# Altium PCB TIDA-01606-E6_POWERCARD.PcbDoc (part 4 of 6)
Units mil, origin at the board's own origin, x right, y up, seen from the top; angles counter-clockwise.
Board outline 13779.53 x 7874.02 mil, 4 copper layers (Top Layer, Gnd Layer, Pwr Layer, Bottom Layer), stack 94.4 mil thick; 550 components, 292 nets, 1594 pads, 572 vias.
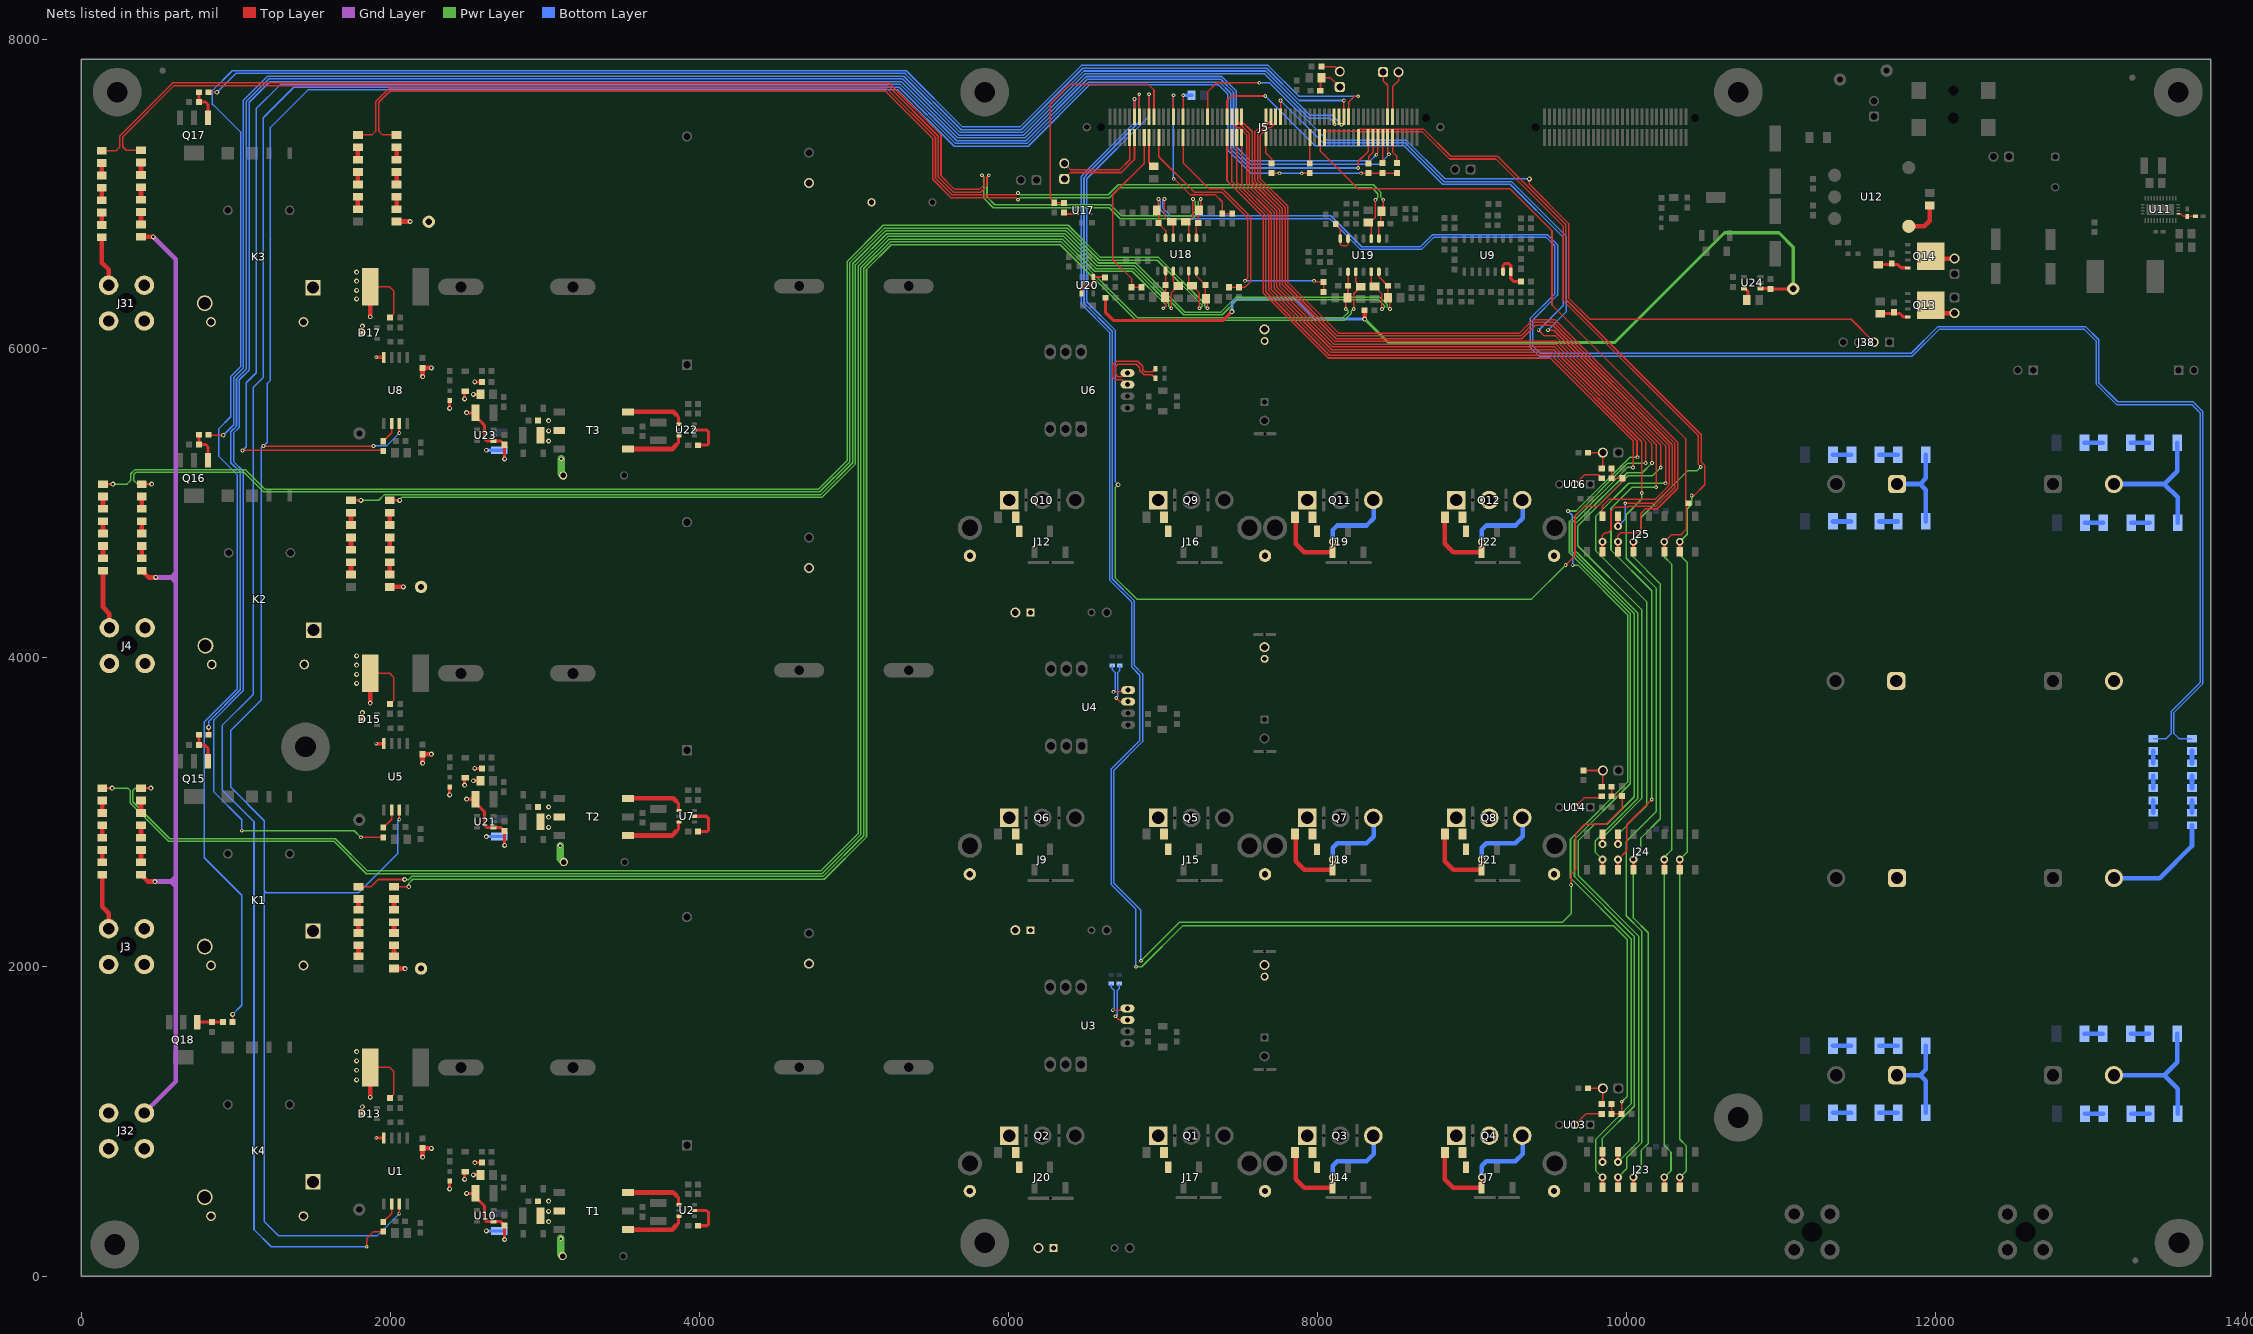
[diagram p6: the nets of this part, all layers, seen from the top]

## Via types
v1: diameter 32, hole 16, Top Layer to Bottom Layer, 336 vias
v2: diameter 24, hole 12, Top Layer to Bottom Layer, 140 vias
v3: diameter 50, hole 28, Top Layer to Bottom Layer, tented both sides, 65 vias
v4: diameter 52, hole 28, Top Layer to Bottom Layer, 14 vias
v5: diameter 19.68, hole 7.87, Top Layer to Bottom Layer, 10 vias
v6: diameter 50, hole 28, Top Layer to Bottom Layer, 7 vias

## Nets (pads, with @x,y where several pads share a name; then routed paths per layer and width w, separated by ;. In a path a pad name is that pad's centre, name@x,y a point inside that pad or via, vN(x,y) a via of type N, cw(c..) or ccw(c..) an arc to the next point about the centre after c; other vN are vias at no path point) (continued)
NetJ5_9: J5.9 J6.2 | length 609.7
  Top Layer w10: J6.2@6361,7199 6401,7159 6720.72,7159 6783.97,7222.25 J5.9@6783.97,7366.21
NetJ5_11: J5.11 J6.1 | length 647.6
  Top Layer w10: J6.1@6361,7099 6402,7140 6730,7140 6815.47,7225.47 J5.11@6815.47,7366.21
NetJ5_17: J5.17 R195.1 | length 205
  Top Layer w12: J5.17@6909.96,7366.21 6909.96,7203.06 R195.1@6939.55,7173.46
NetJ5_32: J5.32 R196.1 | length 200
  Top Layer w10: J5.32@7130.43,7500.07 v2@7130.43,7639.57
  Bottom Layer w20: v2@7130,7640 R196.1@7190.53,7640
  other v2: 7129.99,7640.01
NetJ5_57: J5.57 R34.2 | length 179.7
  Top Layer w10: J5.57@7665.86,7366.21 7665.86,7264.61 7702,7228.47 R34.2@7702,7201.46
NetJ5_75: J5.75 R36.2 | length 165
  Top Layer w10: R36.2@7948.7,7201.46 7949.33,7202.09 J5.75@7949.33,7366.21
NetJ5_101: J5.101 R163.2 | length 183.7
  Top Layer w10: R163.2@8325,7201.46 R163.2@8330,7206.46 ; R163.2@8330,7201.46 R163.2@8330,7206.46 ; J5.101@8358.78,7366.21 8358.77,7270.37 8330,7241.59 R163.2@8330,7206.46
NetJ5_105: J5.105 R164.2 | length 164.5
  Top Layer w10: R164.2@8420,7202.46 8421.77,7204.23 J5.105@8421.77,7366.21
NetJ5_108: J5.108 J11.1 | length 301.2
  Top Layer w10: J11.1@8423.7,7789 8423.7,7733.3 8453.26,7703.74 J5.108@8453.26,7500.07
NetJ5_109: J5.109 R165.2 | length 175.4
  Top Layer w10: J5.109@8484.76,7366.21 8484.76,7273.24 8513,7245 R165.2@8513,7202.46
NetJ5_110: J5.110 J11.2 | length 305.1
  Top Layer w10: J5.110@8484.76,7500.07 8484.76,7694.36 8523.7,7733.3 J11.2@8523.7,7789
NetJ10_1: J10.1 R35.1 R37.1 | length 235.5
  Top Layer w10: R37.1@8017.13,7669 8019.09,7669 8018.79,7669.3 8018.79,7753 8083.33,7753 J10.1@8143.33,7693
NetJ10_2: J10.2 R38.2 | length 132.8
  Top Layer w10: R38.2@8023.83,7825 8111.33,7825 J10.2@8143.33,7793
NetJ26_2: J26.2 Q13.5 Q13.6 Q13.7 Q13.8 Q13.9@11966.81,6281 | length 181
  Top Layer w30: Q13.9@11940,6230 J26.2@12121,6230
NetJ27_2: J27.2 R55.1 R58.1 | length 190
  Top Layer w10: R55.1@9750,1215.2 J27.2@9845,1215.2 R58.1@9845,1120.24
NetJ28_2: J28.2 Q14.5 Q14.6 Q14.7 Q14.8 Q14.9@11967.57,6597.75 | length 173.2
  Top Layer w30: Q14.9@11948.8,6583 J28.2@12121.99,6583
NetJ29_2: J29.2 R64.1 R65.1 | length 223.3
  Top Layer w10: R64.1@9720.23,3271.27 J29.2@9845,3271.27 R65.1@9845,3172.76
NetJ30_2: J30.2 R91.1 R92.1 | length 202.7
  Top Layer w10: R91.1@9750,5327.33 J30.2@9845,5327.33 9845,5240.87 R92.1@9830,5225.87
NetQ13_4: Q13.4 R59.2 R60.2 | length 185.7
  Top Layer w20: R59.2@11640.79,6226 11642.04,6227.25 11767.25,6227.25 11788.5,6206 Q13.4@11817.2,6206
NetQ14_4: Q14.4 R66.2 R76.2 | length 185.7
  Top Layer w20: R66.2@11626.54,6543.76 11627.79,6545 11753,6545 11774.25,6523.76 Q14.4@11802.96,6523.76
NetQ15_1: Q15.1 R197.2 R201.2 | length 217.3
  Top Layer w20: R197.2@762.5,3501.99 R201.2@762.5,3436 800,3436 821.55,3414.45 Q15.1@821.55,3331.17
NetQ16_1: Q16.1 R198.2 R204.2 | length 216.8
  Top Layer w20: R198.2@762.5,5443.99 R204.2@762.5,5380 806,5380 821.55,5364.45 Q16.1@821.55,5277.17
NetQ17_1: Q17.1 R199.2 R202.2 | length 214.2
  Top Layer w20: R199.2@762.5,7658.99 R202.2@762.5,7596 805,7596 821.55,7579.45 Q17.1@821.55,7494.17
NetQ18_1: Q18.1 R200.2 R203.2 | length 166.3
  Top Layer w20: Q18.1@751.55,1643.17 847.68,1643.17 R203.2@848,1643.5 917,1643.5 R200.2@917.5,1644
NetR1_1: R1.1 R3.2 | length 118.9
  Bottom Layer w30: R1.1@12961.25,5392.45 R3.2@13080.15,5392.45
NetR2_1: R2.1 R4.2 | length 118.9
  Bottom Layer w30: R2.1@12964.25,4874.55 R4.2@13083.15,4874.55
NetR3_1: R3.1 R6.2 | length 118.9
  Bottom Layer w30: R3.1@13261.25,5392.45 R6.2@13380.15,5392.45
NetR4_1: R4.1 R7.2 | length 118.9
  Bottom Layer w30: R4.1@13264.25,4874.55 R7.2@13383.15,4874.55
NetR9_1: R9.1 R12.2 | length 118.9
  Bottom Layer w30: R12.2@11634.4,4882.55 R9.1@11753.3,4882.55
NetR10_1: R10.1 R13.2 | length 118.9
  Bottom Layer w30: R13.2@11634.4,5314.45 R10.1@11753.3,5314.45
NetR12_1: R12.1 R14.2 | length 118.9
  Bottom Layer w30: R14.2@11334.4,4882.55 R12.1@11453.3,4882.55
NetR13_1: R13.1 R15.2 | length 118.9
  Bottom Layer w30: R15.2@11334.4,5314.45 R13.1@11453.3,5314.45
NetR19_1: R19.1 U3.11 | length 280
  Top Layer w10: v2(6675.35,1721.06) 6758.26,1721.06 U3.11@6769.7,1732.5
  Bottom Layer w10: R19.1@6665.35,1889.57 6665.35,1866.94 6685.35,1846.94 6685.35,1731.06 v2(6675.35,1721.06)
NetR20_1: R20.1 U3.12 | length 335
  Top Layer w10: v2@6692.61,1683.8 v2(6692.61,1681.06) 6716.17,1657.5 U3.12@6769.7,1657.5
  Bottom Layer w10: v2(6692.61,1681.06) 6703.22,1691.67 6703.22,1846.56 6715.28,1858.62 R20.1@6715.28,1889.57 ; U3.12@6742.5,1657.5 U3.12@6770,1657.5
NetR21_1: R21.1 U4.11 | length 280
  Top Layer w10: v2(6680,3780) 6762.92,3780 U4.11@6774.35,3791.44
  Bottom Layer w10: R21.1@6670,3948.5 6670,3925.87 6690,3905.87 6690,3790 v2(6680,3780)
NetR22_1: R22.1 U4.12 | length 307.5
  Top Layer w10: v2@6697.27,3742.73 v2(6697.27,3740) 6720.83,3716.44 U4.12@6774.35,3716.44
  Bottom Layer w10: v2(6697.27,3740) 6707.87,3750.61 6707.87,3905.5 6719.93,3917.56 R22.1@6719.93,3948.5
NetR23_1: R23.1 U6.11 | length 453.5
  Top Layer w9: U6.11@6770,5842.5 6752.36,5842.5 6729.41,5819.55 6707.71,5819.55 6692.61,5834.65 6692.61,5884.92 6707.69,5900 6828.24,5900 6850,5878.24 6850,5860 6880,5830 6928.5,5830 R23.1@6948.5,5810
NetR24_1: R24.1 U6.12 | length 528
  Top Layer w9: U6.12@6770,5767.5 6763.91,5767.5 6731.41,5800 6690,5800 6675.35,5814.65 6675.35,5895.59 6699.76,5920 6837,5920 6870,5887 6870,5863.86 6882.37,5851.5 6930,5851.5 R24.1@6948.5,5870
NetR42_2: R42.2 R43.1 | length 80
  Top Layer w30: R42.2@137.45,2677 R43.1@137.45,2757
NetR43_2: R43.2 R44.1 | length 80
  Top Layer w30: R43.2@137.45,2837 R44.1@137.45,2917
NetR44_2: R44.2 R45.1 | length 80
  Top Layer w30: R44.2@137.45,2997 R45.1@137.45,3077
NetR48_2: R48.2 R49.1 | length 80
  Top Layer w30: R48.2@388,2677 R49.1@388,2757
NetR49_2: R49.2 R50.1 | length 80
  Top Layer w30: R49.2@388,2837 R50.1@388,2917
NetR50_2: R50.2 R51.1 | length 80
  Top Layer w30: R50.2@388,2997 R51.1@388,3077
NetR52_1: R52.1 U13.2 | length 204.5
  Top Layer w10: U13.2@9663.54,977.94 9734.8,1049.2 R52.1@9838.5,1049.2
NetR54_1: R54.1 R57.2 U11.12 | length 120.1
  Top Layer w10: U11.12@13566.8,6871.62 13586.38,6871.62 13601.62,6856.38 R57.2@13626,6856.38 13679.76,6856.38 R54.1@13680.38,6857
NetR62_1: R62.1 U14.2 | length 204.5
  Top Layer w10: U14.2@9663.54,3034 9723.53,3094 9827.24,3094 R62.1@9838.5,3105.27
NetR67_2: R67.2 R68.1 | length 80
  Top Layer w30: R67.2@142.45,4644 R68.1@142.45,4724
NetR68_2: R68.2 R69.1 | length 80
  Top Layer w30: R68.2@142.45,4804 R69.1@142.45,4884
NetR69_2: R69.2 R70.1 | length 80
  Top Layer w30: R69.2@142.45,4964 R70.1@142.45,5044
NetR72_2: R72.2 U12.4 | length 249.1
  Top Layer w30: U12.4@11824.66,6792.04 11924.04,6792.04 11959.7,6827.7 R72.2@11959.7,6927
NetR73_1: R73.1 R110.2 | length 80
  Top Layer w30: R110.2@393,4644 R73.1@393.01,4724
NetR73_2: R73.2 R74.1 | length 80
  Top Layer w30: R73.2@393.01,4804 R74.1@393,4884
NetR74_2: R74.2 R75.1 | length 80
  Top Layer w30: R74.2@393,4964 R75.1@393,5044
NetR77_1: R77.1 U16.2 | length 212.1
  Top Layer w10: U16.2@9664.61,5122.01 9726.6,5184 9815.83,5184 R77.1@9838.5,5161.33 R77.1@9835.33,5161.33
NetR80_2: R80.2 R81.1 | length 80
  Top Layer w30: R80.2@134.45,6801 R81.1@134.45,6881
NetR81_2: R81.2 R82.1 | length 80
  Top Layer w30: R81.2@134.45,6961 R82.1@134.45,7041
NetR82_2: R82.2 R83.1 | length 80
  Top Layer w30: R82.2@134.45,7121 R83.1@134.45,7201
NetR85_2: R85.2 R86.1 | length 80
  Top Layer w30: R85.2@388,6804 R86.1@388,6884
NetR86_2: R86.2 R87.1 | length 80
  Top Layer w30: R86.2@388,6964 R87.1@388,7044
NetR87_2: R87.2 R88.1 | length 80
  Top Layer w30: R87.2@388,7124 R88.1@388,7204
NetR90_2: R90.2 U2.5 | length 239.7
  Top Layer w20: U2.5@3973.14,425 4045,425 4060,410 4060,336 4050,326 R90.2@3991.5,326
NetR93_1: R93.1 U17.3 | length 81
  Top Layer w15: R93.1@6359,6872 6359.59,6871.41 U17.3@6439.71,6871.41
NetR95_2: R95.2 R96.1 | length 70
  Top Layer w30: R95.2@1795,2070 R96.1@1795,2140
NetR96_2: R96.2 R97.1 | length 70
  Top Layer w30: R96.2@1795,2220 R97.1@1795,2290
NetR97_2: R97.2 R98.1 | length 70
  Top Layer w30: R97.2@1795,2370 R98.1@1795,2440
NetR100_2: R100.2 R101.1 | length 70
  Top Layer w30: R100.2@2025,2070 R101.1@2025,2140
NetR101_2: R101.2 R102.1 | length 70
  Top Layer w30: R101.2@2025,2220 R102.1@2025,2290
NetR102_2: R102.2 R103.1 | length 70
  Top Layer w30: R102.2@2025,2370 R103.1@2025,2440
NetR106_2: R106.2 R107.1 | length 80
  Top Layer w30: R106.2@1746.45,4539 R107.1@1746.45,4619
NetR107_2: R107.2 R108.1 | length 80
  Top Layer w30: R107.2@1746.45,4699 R108.1@1746.45,4779
NetR108_2: R108.2 R109.1 | length 80
  Top Layer w30: R108.2@1746.45,4859 R109.1@1746.45,4939
NetR112_2: R112.2 R113.1 | length 80
  Top Layer w30: R112.2@1997,4539 R113.1@1997,4619
NetR113_2: R113.2 R114.1 | length 80
  Top Layer w30: R113.2@1997,4699 R114.1@1997,4779
NetR114_2: R114.2 R115.1 | length 80
  Top Layer w30: R114.2@1997,4859 R115.1@1997,4939
NetR118_2: R118.2 R119.1 | length 80
  Top Layer w30: R118.2@1791.06,6903 R119.1@1791.06,6983
NetR119_2: R119.2 R120.1 | length 80
  Top Layer w30: R119.2@1791.06,7063 R120.1@1791.06,7143
NetR120_2: R120.2 R121.1 | length 80
  Top Layer w30: R120.2@1791.06,7223 R121.1@1791.06,7303
NetR123_2: R123.2 R124.1 | length 80
  Top Layer w30: R123.2@2041.61,6903 R124.1@2041.61,6983
NetR124_2: R124.2 R125.1 | length 80
  Top Layer w30: R124.2@2041.61,7063 R125.1@2041.61,7143
NetR125_2: R125.2 R126.1 | length 80
  Top Layer w30: R125.2@2041.61,7223 R126.1@2041.61,7303
NetR129_1: R129.1 U9.13 U9.14 | length 258.9
  Top Layer w20: U9.13@9199.7,6497.89 9199.7,6538.61 9211.09,6550 9238.37,6550 9249.7,6538.67 U9.14@9249.7,6497.89 9249.7,6454.29 9268.79,6435.2 R129.1@9316.21,6435.2
NetR132_2: R132.2 R133.1 | length 80
  Bottom Layer w30: R132.2@13406,2997.45 R133.1@13406,3077.45
NetR133_2: R133.2 R134.1 | length 80
  Bottom Layer w30: R133.2@13406,3157.45 R134.1@13406,3237.45
NetR134_2: R134.2 R135.1 | length 80
  Bottom Layer w30: R134.2@13406,3317.45 R135.1@13406,3397.45
NetR137_2: R137.2 R138.1 | length 80
  Bottom Layer w30: R137.2@13656.55,2997.45 R138.1@13656.55,3077.45
NetR138_2: R138.2 R166.1 | length 80
  Bottom Layer w30: R138.2@13656.55,3157.45 R166.1@13656.55,3237.45
NetR140_1: R140.1 U19.13 U19.14 | length 239.3
  Top Layer w10: R140.1@8117.7,6806.5 8146.83,6777.37 U19.14@8146.83,6712.46 8146.83,6675.17 8157,6665 8187,6665 8196.83,6674.83 U19.13@8196.83,6712.46
NetR143_1: R143.1 U20.1 U20.4 | length 238.7
  Top Layer w15: U20.4@6472.6,6355.87 6472.6,6390 6492.6,6410 6530.16,6410 6547.4,6427.24 U20.1@6547.4,6464.13 6621.13,6464.13 R143.1@6623.77,6461.5
NetR146_1: R146.1 U1.6 | length 136.5
  Top Layer w10: R146.1@1955,351.5 2009.45,405.94 U1.6@2009.45,465.43
NetR149_1: R149.1 U5.6 | length 136.5
  Top Layer w10: R149.1@1955,2901.5 2009.45,2955.94 U5.6@2009.45,3015.43
NetR152_1: R152.1 U8.6 | length 136.5
  Top Layer w10: R152.1@1955,5401.5 2009.45,5455.94 U8.6@2009.45,5515.43
NetR154_2: R154.2 U7.5 | length 239.7
  Top Layer w20: U7.5@3973.14,2975 4045,2975 4060,2960 4060,2886 4050,2876 R154.2@3991.5,2876
NetR160_2: R160.2 U22.5 | length 239.7
  Top Layer w20: U22.5@3973.14,5475 4045,5475 4060,5460 4060,5386 4050,5376 R160.2@3991.5,5376
NetR166_2: R166.2 R205.1 | length 80
  Bottom Layer w30: R166.2@13656.55,3317.45 R205.1@13656.55,3397.45
NetR177_2: R177.2 U24.5 | length 89.3
  Top Layer w20: U24.5@10757.47,6389.64 10764.36,6389.64 10783.14,6370.86 R177.2@10783.14,6315.04
NetR180_1: R180.1 R182.2 | length 118.9
  Bottom Layer w30: R180.1@12961.25,1567.97 R182.2@13080.15,1567.97
NetR181_1: R181.1 R183.2 | length 118.9
  Bottom Layer w30: R181.1@12964.25,1050.07 R183.2@13083.15,1050.07
NetR182_1: R182.1 R184.2 | length 118.9
  Bottom Layer w30: R182.1@13261.25,1567.97 R184.2@13380.15,1567.97
NetR183_1: R183.1 R185.2 | length 118.9
  Bottom Layer w30: R183.1@13264.25,1050.07 R185.2@13383.15,1050.07
NetR186_1: R186.1 R188.2 | length 118.9
  Bottom Layer w30: R188.2@11634.4,1489.97 R186.1@11753.3,1489.97
NetR187_1: R187.1 R189.2 | length 118.9
  Bottom Layer w30: R189.2@11634.4,1058.07 R187.1@11753.3,1058.07
NetR188_1: R188.1 R190.2 | length 118.9
  Bottom Layer w30: R190.2@11334.4,1489.97 R188.1@11453.3,1489.97
NetR189_1: R189.1 R191.2 | length 118.9
  Bottom Layer w30: R191.2@11334.4,1058.07 R189.1@11453.3,1058.07
NetT1_1: T1.1 U2.3 | length 390.2
  Top Layer w20: 3851.87,328.87 3864.87,341.87 3864.87,387.6 U2.3@3865.74,388.47
  Top Layer w30: T1.1@3538.64,300.92 3823.92,300.92 3851.87,328.87
NetT1_3: T1.3 U2.1 | length 385.6
  Top Layer w20: 3851,522 3864,509 3864,463.27 U2.1@3864.87,462.4
  Top Layer w30: T1.3@3538.64,541.08 3831.92,541.08 3851,522
NetT2_1: T2.1 U7.3 | length 390.2
  Top Layer w20: 3851.87,2878.87 3864.87,2891.87 3864.87,2937.6 U7.3@3865.74,2938.47
  Top Layer w30: T2.1@3538.64,2850.92 3823.92,2850.92 3851.87,2878.87
NetT2_3: T2.3 U7.1 | length 385.6
  Top Layer w20: 3851,3072 3864,3059 3864,3013.27 U7.1@3864.87,3012.4
  Top Layer w30: T2.3@3538.64,3091.08 3831.92,3091.08 3851,3072
NetT3_1: T3.1 U22.3 | length 390.2
  Top Layer w20: 3851.87,5378.87 3864.87,5391.87 3864.87,5437.6 U22.3@3865.74,5438.47
  Top Layer w30: T3.1@3538.64,5350.92 3823.92,5350.92 3851.87,5378.87
NetT3_3: T3.3 U22.1 | length 385.6
  Top Layer w20: 3851,5572 3864,5559 3864,5513.27 U22.1@3864.87,5512.4
  Top Layer w30: T3.3@3538.64,5591.08 3831.92,5591.08 3851,5572
NEU: J32.1 K4.2 R48.1 R85.1 R110.1 RF4.1 | length 6552.2
  Top Layer w30: R48.1@388,2597 432,2553 v1(478,2553) ; R85.1@388,6724 v1(467,6724) ; R110.1@393,4564 437,4520 v1(483,4520)
  Gnd Layer w30: J32.1@409.55,1055.56 613,1259.01 613,2554 ; v1(467,6724) 613,6578 613,4520 ; v1(478,2553) 612,2553 613,2554 ; v1(483,4520) 613,4520 ; 613,2521 581,2553 613,2585 ; 613,4489 582,4520 613,4551 ; 613,2554 613,4520
PA_N: C83.2 R39.2 R45.2 U18.2 | length 11462
  Top Layer w10: v2@7001.41,6262 7016.16,6276.75 C83.2@7016.16,6413 7016.24,6413.08 U18.2@7016.24,6502.89
  Top Layer w15: R45.2@137.45,3157 v1(200.91,3157)
  Pwr Layer w10: v1(200.91,3157) 302.1,3157 317.24,3141.85 317.24,3062.03 567.15,2812.13 1637.49,2812.13 1845.9,2603.71 4792.99,2603.71 5045.75,2856.47 5045.75,6527.3 5227.19,6708.75 6350.3,6708.75 6558.18,6500.87 6801.05,6500.87 7018.8,6283.12 7018.8,6274.84 7005.96,6262 v2(7001.74,6262)
PA_P: R51.2 R56.2 U18.3 | length 11486.5
  Top Layer w10: v2(7053.74,6262) 7053.74,6360.63 7097.06,6403.94 7066.24,6434.76 U18.3@7066.24,6502.89
  Top Layer w15: R51.2@388,3157 v1(451.46,3157)
  Pwr Layer w10: v1(451.46,3157) 349.96,3157 335.12,3142.15 335.12,3069.43 574.55,2830 1644.89,2830 1853.31,2621.58 4785.58,2621.58 5027.87,2863.87 5027.87,6534.71 5219.79,6726.62 6357.7,6726.62 6565.59,6518.74 6808.46,6518.74 7036.67,6290.52 7036.67,6275.27 7049.95,6262 v2(7053.74,6262)
PB_N: C85.2 R61.2 R70.2 U18.6 | length 9224.1
  Top Layer w10: U18.6@7216.24,6502.89 7216.24,6470.67 C85.2@7273.91,6413 7273.91,6336.5 7287.41,6323 v2(7287.41,6262)
  Top Layer w15: R70.2@142.45,5124 v1(205.91,5124)
  Pwr Layer w10: v1(205.91,5124) 298.08,5124 322.24,5148.16 322.24,5191.55 348.57,5217.87 1062.13,5217.87 1187.87,5092.13 4772.13,5092.13 4956.38,5276.38 4956.38,6564.32 5190.17,6798.12 6387.32,6798.12 6595.2,6590.24 6970.64,6590.24 7270.35,6290.52 7270.35,6274.84 7276.21,6268.98 7276.64,6268.98 7283.62,6262 v2(7287.41,6262)
PB_P: R75.2 R78.2 U18.5 | length 9163.8
  Top Layer w10: U18.5@7166.24,6502.89 7166.24,6428.87 7235.41,6359.7 v2(7235.41,6262)
  Top Layer w15: R75.2@393,5124 v1(456.46,5124)
  Pwr Layer w10: v1(456.46,5124) 364.58,5124 340.12,5148.45 340.12,5184.14 355.98,5200 1054.72,5200 1180.47,5074.25 4779.53,5074.25 4974.25,5268.97 4974.25,6556.92 5197.58,6780.24 6379.91,6780.24 6587.8,6572.36 6963.23,6572.36 7252.47,6283.12 7252.47,6274.84 7246.62,6268.98 7246.18,6268.98 7239.2,6262 v2(7235.41,6262)
PC_N: C87.2 R79.2 R83.2 U18.9 | length 8421.2
  Top Layer w10: R83.2@134.45,7281 225.81,7281 251.67,7306.86 251.67,7377.22 594.44,7720 5225.83,7720 5563.62,7382.21 5563.62,7118.21 5651.15,7030.68 5813.12,7030.68 5842.21,7059.77 5842.21,7108.8 v2(5829.14,7121.86) ; U18.9@7216.24,6717.46 7216.24,6802.33 C87.2@7227.91,6814 7227.91,6890.5 7244.41,6907 v2(7244.41,6968)
  Pwr Layer w10: v2(5829.14,7121.86) 5841.14,7109.86 5841.14,6973.08 5902.22,6912 6651.72,6912 6723.72,6840 7190.28,6840 7228.91,6878.63 7228.91,6952.5 v2(7244.41,6968)
PC_P: R88.2 R89.2 U18.10 | length 8378
  Top Layer w10: R88.2@388,7284 292.4,7284 269.54,7306.86 269.54,7369.82 601.85,7702.13 5218.43,7702.13 5545.75,7374.81 5545.75,7110.81 5643.74,7012.81 5820.52,7012.81 5860.08,7052.37 5860.08,7108.8 v2(5873.14,7121.86) ; U18.10@7166.24,6717.46 7166.24,6801.17 R89.2@7146.41,6821 7158.41,6821 7193.54,6856.13 7193.54,6967.87 v2(7193.41,6968)
  Pwr Layer w10: v2(5873.14,7121.86) 5861.14,7109.86 5861.14,6981.36 5910.51,6932 6660,6932 6732,6860 7182,6860 7208.91,6886.91 7208.91,6952.5 v2(7193.41,6968)
PD_N: C133.2 R131.2 R135.2 U18.13 | length 10887.5
  Top Layer w10: v2@6970,6970 v2(6970,6968) 6970,6900 6960,6890 6971.5,6878.5 C133.2@6971.5,6813.93 6971.5,6810 7016.24,6765.25 U18.13@7016.24,6717.46
  Bottom Layer w10: v2(6970,6968) 6980.77,6957.23 6980.77,6902.6 7041.24,6842.13 8077.87,6842.13 8277.87,6642.13 8672.4,6642.13 8750.28,6720 9480,6720 9534.29,6665.71 9534.29,6354.29 9374.76,6194.76 9374.76,6009.96 9432.6,5952.13 11847.4,5952.13 12020.35,6125.07 12960.88,6125.07 13036.1,6049.85 13036.1,5770.9 13168.72,5638.28 13655.72,5638.28 13709.75,5584.25 13709.75,3841.03 13522.34,3653.62 13522.34,3510 13489.79,3477.45 R135.2@13406,3477.45
PD_P: R205.2 R206.2 U18.12 | length 10888.6
  Top Layer w10: v2@7009.28,6967.87 7009.28,6856.13 7044.41,6821 R206.2@7056.41,6821 7066.24,6811.17 U18.12@7066.24,6717.46
  Bottom Layer w10: v2(7009.41,6968) 6998.64,6957.23 6998.64,6910 7048.64,6860 8085.28,6860 8285.28,6660 8665,6660 8742.87,6737.87 9487.4,6737.87 9552.17,6673.11 9552.17,6346.89 9392.64,6187.36 9392.64,6017.36 9440,5970 11840,5970 12012.94,6142.94 12968.28,6142.94 13053.97,6057.25 13053.97,5778.3 13176.13,5656.15 13663.13,5656.15 13727.62,5591.65 13727.62,3833.62 13540.21,3646.21 13540.21,3510 13572.76,3477.45 R205.2@13656.55,3477.45
PGND: C1.2 C2.2 C3.2 C4.2 C5.2 C6.1 C7.1 C11.1 C12.1 C13.1 C73.2 C74.2 C75.1 C76.1 C120.2 C121.2 C122.2 C127.1 C128.1 C129.1 C130.2 K4.1 Q4.2 Q8.2 Q12.2 R6.1 R7.1 R9.2 R10.2 R16.1 R17.1 R18.1 R100.1 R112.1 R123.1 R137.1 R184.1 R185.1 R186.2 R187.2 RF4.2 TP4.1 TP5.1 TP6.1 TP7.1 TP8.1 TP9.1 TP10.1 TP11.1 TP12.1 TP13.1 TP14.1 TP15.1 | length 4024.7
  Top Layer w30: R112.1@1997,4459 v1(2084.91,4459) ; R100.1@2025,1990 v1(2096.5,1990) ; R123.1@2041.61,6823 v1(2129.61,6823)
  Bottom Layer w30: C6.1@11748.7,1300 11897.48,1300 ; C7.1@11748.7,5124.48 11897.48,5124.48 ; R187.2@11934.4,1058.07 11934.4,1263.08 11897.48,1300 ; R186.2@11934.4,1489.97 11934.4,1336.92 11897.48,1300 ; R9.2@11934.4,4882.55 11934.4,5087.56 11897.48,5124.48 ; R10.2@11934.4,5314.45 11934.4,5161.4 11897.48,5124.48 ; C5.2@13151.55,1300 13477.48,1300 ; C74.2@13151.55,2575 13448.95,2575 13656.55,2782.6 R137.1@13656.55,2917.45 ; C4.2@13151.55,5124.48 13477.48,5124.48 ; R184.1@13561.25,1567.97 13561.25,1383.77 13477.48,1300 ; R6.1@13561.25,5392.45 13561.25,5208.25 13477.48,5124.48 ; R185.1@13564.25,1050.07 13564.25,1213.23 13477.48,1300 ; R7.1@13564.25,4874.55 13564.25,5037.71 13477.48,5124.48
PH_A: J3.1 K1.2 R42.1 RF1.1 | length 366.4
  Top Layer w30: R42.1@137.45,2597 137.45,2389.55 178.45,2348.55 J3.1@178.45,2247.56
PH_B: J4.1 K2.2 R67.1 RF2.1 | length 386.4
  Top Layer w30: R67.1@142.45,4564 142.45,4327.55 183.45,4286.55 J4.1@183.45,4194.56
PH_C: J31.1 K3.2 R80.1 RF3.1 | length 328.7
  Top Layer w30: R80.1@134.45,6721 134.45,6556.55 178.45,6512.55 J31.1@178.45,6410.56
PWM_EN: J5.95 J23.8 J24.8 J25.8 | length 8762.6
  Top Layer w10: J5.95@8264.29,7366.21 8264.29,7391.39 8275.6,7402.71 8678.13,7402.71 8853.48,7227.35 9153.84,7227.35 9587.91,6793.29 9587.91,6312.34 10463.62,5436.63 10463.62,5250.35 v2(10478.98,5235)
  Top Layer w20: J23.8@10042.93,574.56 v3(10042.93,638.93) ; J24.8@10042.93,2630.62 v3(10042.93,2694.99) ; J25.8@10042.93,4686.69 v3(10042.93,4751.06)
  Pwr Layer w10: v3(10042.93,638.93) 10093,689 10093,812 10139,858 10139,2221 10042.93,2317.07 v3(10042.93,2694.99) 10092,2744.06 10092,2834.72 10217,2959.72 10217,4478 10042.93,4652.07 v3(10042.93,4751.06) 10090,4798.13 10090,4907 10392.39,5209.39 10453.37,5209.39 v2(10478.98,5235)
PWM_Q1A: J5.49 J23.5 | length 9386.5
  Top Layer w10: J5.49@7413.89,7366.21 7413.89,7087.38 7647.01,6854.27 7647.01,6361.55 8068.56,5940 9505.26,5940 10041,5404.25 v2(10041,5232)
  Top Layer w20: v3(9942.93,738.93) J23.5@9942.93,803.3
  Pwr Layer w10: v3(9942.93,738.93) 10079,875 10079,2198 9687,2590 9687,2819 9791,2923 9870,2923 10048,3101 10048,4286.72 9647.34,4687.38 9647.34,4875.06 10004.28,5232 v2(10041,5232)
PWM_Q1B: J5.50 J24.5 | length 7650.3
  Top Layer w10: J5.50@7413.89,7500.07 7413.89,7606.89 7442,7635 v2(7661,7635) ; v2(9430,6120) 9467.01,6082.99 9539.21,6082.99 10251,5371.2 v2(10251,5129)
  Top Layer w20: v3(9942.93,2794.99) J24.5@9942.93,2859.36
  Pwr Layer w10: v3(9942.93,2794.99) 9942.93,2857.93 10128,3043 10128,4364 9798,4694 9798,4914 10013,5129 v2(10251,5129)
  Bottom Layer w10: v2(7661,7635) 7981.75,7314.25 8557.59,7314.25 8808.59,7063.25 9246.87,7063.25 9587.91,6722.21 9587.91,6277.91 v2(9430,6120)
PWM_Q1C: J5.58 J25.5 | length 5062.6
  Top Layer w10: J5.58@7665.86,7500.07 7665.86,7473.74 7594.25,7402.13 7594.25,7083.97 7772.13,6906.09 7772.13,6413.38 8120.38,6065.12 9320.95,6065.12 9407.96,6152.13 9520.63,6152.13 10293.75,5379.01 10293.75,5111.29 10182.46,5000 v2(9990,5000)
  Top Layer w20: v3(9942.93,4851.06) J25.5@9942.93,4915.43
  Bottom Layer w10: v3(9942.93,4851.06) 9990,4898.13 v2(9990,5000)
PWM_Q2A: J5.53 J23.6 | length 9029.2
  Top Layer w10: J5.53@7476.89,7366.21 7476.89,7074.95 7682.76,6869.08 7682.76,6376.36 8083.37,5975.75 9520.06,5975.75 10097,5398.81 v2(10097,5066)
  Top Layer w20: J23.6@9942.93,574.56 v3(9942.93,638.93)
  Pwr Layer w10: v3(9942.93,638.93) 9999.54,695.54 9999.54,766.7 10098,865.15 10098,2230 9996,2332 9996,2812 10192,3008 10192,4448 9996,4644 9996,4926 10097,5027 v2(10097,5066)
PWM_Q2B: J5.54 J24.6 | length 7247.3
  Top Layer w10: J5.54@7476.89,7500.07 7476.89,7474.65 7558.5,7393.04 7558.5,7069.16 7736.38,6891.29 7736.38,6398.57 8105.58,6029.37 9542.27,6029.37 10190,5381.64 v2(10190,5104) ; v3(9942.93,2694.99) 9999.54,2751.61 9999.54,2920.54 v2(10162,3083)
  Top Layer w20: J24.6@9942.93,2630.62 v3(9942.93,2694.99)
  Pwr Layer w10: v2(10162,3083) 10162,4434 9898,4698 9898,4968 10034,5104 v2(10190,5104)
PWM_Q2C: J5.62 J25.6 | length 5194.7
  Top Layer w10: J5.62@7728.85,7500.07 7728.85,7464.36 7694.65,7430.16 7678.14,7430.16 7630,7382.02 7630,7098.78 7807.87,6920.9 7807.87,6428.18 8135.19,6100.87 9306.14,6100.87 9393.4,6188.13 9535.18,6188.13 10329.5,5393.81 10329.5,5096.49 10197.26,4964.25 10121.35,4964.25 10090,4932.9 10090,4830 10070,4810 9960,4810 9942.93,4792.93 v3(9942.93,4751.06)
  Top Layer w20: J25.6@9942.93,4686.69 v3(9942.93,4751.06)
PWM_Q3A: J5.51 J23.4 | length 9574.3
  Top Layer w10: J5.51@7445.39,7366.21 7445.39,7081.17 7664.88,6861.67 7664.88,6368.95 8075.96,5957.87 9512.66,5957.87 10058.87,5411.66 10058.87,5411.13 10066.32,5403.68 10066.32,5299.68 v2(10069,5297)
  Top Layer w20: J23.4@9842.93,574.56 v3(9842.93,638.93)
  Pwr Layer w10: v2(9620,4950) 9671.72,4950 10018.72,5297 v2(10069,5297) ; v2(9650,4600) 9684.17,4600 10005,4279.17 10005,3196 9636,2827 9636,2575 10028,2183 10028,1114 9798,884 9798,683.86 v3(9842.93,638.93)
  Bottom Layer w10: v2(9620,4950) 9647.34,4922.66 9647.34,4677.34 9650,4674.68 v2(9650,4600)
PWM_Q3B: J5.52 J24.4 | length 7413
  Top Layer w10: J5.52@7445.39,7500.07 7445.39,7464.22 7479.45,7430.16 7496.1,7430.16 7540.63,7385.63 7540.63,7061.76 7718.5,6883.88 7718.5,6391.17 8098.17,6011.5 9534.87,6011.5 10163,5383.36 v2(10163,5260)
  Top Layer w20: J24.4@9842.93,2630.62 v3(9842.93,2694.99)
  Pwr Layer w10: v3(9842.93,2694.99) 9797,2740.92 9797,2816 10072,3091 10072,4288 9690,4670 9665.21,4694.79 9665.21,4865.21 9700,4900 10003,5198 10101,5198 v2(10163,5260)
PWM_Q3C: J5.60 J25.4 | length 5267
  Top Layer w10: J5.60@7697.36,7500.07 7697.36,7474.66 7612.13,7389.42 7612.13,7091.37 7790,6913.5 7790,6420.78 8127.79,6082.99 9313.55,6082.99 9400.56,6170 9528.03,6170 10311.62,5386.41 10311.62,5103.89 10189.86,4982.13 10012.64,4982.13 10005.64,4975.13 9923.13,4975.13 9898,4950 9898,4830 9878,4810 9860,4810 9842.93,4792.93 v3(9842.93,4751.06)
  Top Layer w20: J25.4@9842.93,4686.69 v3(9842.93,4751.06)
PWM_Q4A: J5.55 J23.3 | length 9445.4
  Top Layer w10: J5.55@7508.38,7366.21 7508.38,7068.73 7700.63,6876.48 7700.63,6383.76 8090.77,5993.62 9527.47,5993.62 10122,5399.09 v2(10122,5260)
  Top Layer w20: v3(9842.93,738.93) J23.3@9842.93,803.3
  Pwr Layer w10: v3(9842.93,738.93) 9842.93,892.93 10049,1099 10049,2198 9662,2585 9662,2824 10023,3185 10023,4286.44 9629.46,4679.98 9629.46,4882.47 10007,5260 v2(10122,5260)
PWM_Q4B: J5.56 J24.3 | length 7327.7
  Top Layer w10: J5.56@7508.38,7500.07 7508.38,7471.62 7576.38,7403.62 7576.38,7076.57 7754.25,6898.69 7754.25,6405.97 8112.98,6047.24 9549.68,6047.24 10220,5376.92 10220,5237 v2@10222,5235
  Top Layer w20: v3(9842.93,2794.99) J24.3@9842.93,2859.36
  Pwr Layer w10: v3(9842.93,2794.99) 9842.93,2836.65 10096,3089.72 10096,4313 9683.09,4725.91 9683.09,4852.81 10008.28,5178 10166,5178 v2(10220,5232) v2@10220,5237
PWM_Q4C: J5.64 J25.3 | length 4880.8
  Top Layer w10: J5.64@7760.35,7500.07 v2(7760.38,7606) ; v2(9490,6120) 9527.48,6120 10275.87,5371.6 10275.87,5118.7 10182.05,5024.87 9884.87,5024.87 9842.93,4982.93 J25.3@9842.93,4915.43
  Bottom Layer w10: v2(7760.38,7606) 8034.25,7332.13 8564.99,7332.13 8815.99,7081.13 9254.28,7081.13 9610,6725.4 9610,6240 v2(9490,6120)
Q1A: J17.1 Q1.1 R168.2
Q1B: J15.1 Q5.1 R169.2
Q1C: J16.1 Q9.1 R170.2
Q2A: J20.1 Q2.1 R192.2
Q2B: J9.1 Q6.1 R193.2
Q2C: J12.1 Q10.1 R194.2
Q3A: J14.1 Q3.1 R172.1
Q3B: J18.1 Q7.1 R174.1
Q3C: J19.1 Q11.1 R176.1
Q4A: J7.1 Q4.1 R171.2
Q4B: J21.1 Q8.1 R173.2
Q4C: J22.1 Q12.1 R175.2
QA_N: J7.2 J14.2 Q3.3 Q4.3 R171.1 R172.2 | length 1983.7
  Top Layer w30: R172.2@7859.13,800 7859.13,627.09 7914.22,572 J14.2@8097.26,572 v3(8097.26,638.93) ; R171.1@8822.91,800 8822.91,627.09 8878,572 J7.2@9061.04,572 v3(9061.04,638.93)
  Bottom Layer w30: v3(8097.26,638.93) 8097.26,714.98 8126.22,743.94 8316.22,743.94 8362.26,789.98 Q3.3@8362.26,908.93 ; v3(9061.04,638.93) 9061.04,714.98 9090,743.94 9280,743.94 9326.04,789.98 Q4.3@9326.04,908.93
QB_N: J18.2 J21.2 Q7.3 Q8.3 R173.1 R174.2 | length 1983.7
  Top Layer w30: R174.2@7859.13,2856.06 7859.13,2683.15 7914.22,2628.06 J18.2@8097.26,2628.06 v3(8097.26,2694.99) ; R173.1@8822.91,2856.06 8822.91,2683.15 8878,2628.06 J21.2@9061.04,2628.06 v3(9061.04,2694.99)
  Bottom Layer w30: v3(8097.26,2694.99) 8097.26,2771.04 8126.22,2800 8316.22,2800 8362.26,2846.04 Q7.3@8362.26,2964.99 ; v3(9061.04,2694.99) 9061.04,2771.04 9090,2800 9280,2800 9326.04,2846.04 Q8.3@9326.04,2964.99
QC_N: J19.2 J22.2 Q11.3 Q12.3 R175.1 R176.2 | length 1983.7
  Top Layer w30: R176.2@7859.13,4912.13 7859.13,4739.21 7914.22,4684.13 J19.2@8097.26,4684.13 v3(8097.26,4751.06) ; R175.1@8822.91,4912.13 8822.91,4739.21 8878,4684.13 J22.2@9061.04,4684.13 v3(9061.04,4751.06)
  Bottom Layer w30: v3(8097.26,4751.06) 8097.26,4827.1 8126.22,4856.06 8316.22,4856.06 8362.26,4902.1 Q11.3@8362.26,5021.06 ; v3(9061.04,4751.06) 9061.04,4827.1 9090,4856.06 9280,4856.06 9326.04,4902.1 Q12.3@9326.04,5021.06
RDY: J5.79 J23.12 J24.12 J25.12 R167.2 | length 8650
  Top Layer w10: J5.79@8012.32,7366.21 8017.16,7361.37 8017.16,7279.66 8261.45,7035.38 9244.71,7035.38 9516.42,6763.67 9516.42,6282.72 10383.12,5416.02 10383.12,5015.39 10386.31,5012.19 10386.31,4833.09 10350.18,4796.95 10288.83,4796.95 v3(10242.93,4751.06)
  Top Layer w20: J23.12@10242.93,574.56 v3(10242.93,638.93) ; J24.12@10242.93,2630.62 v3(10242.93,2694.99) ; J25.12@10242.93,4686.69 v3(10242.93,4751.06)
  Pwr Layer w10: v3(10242.93,638.93) 10286.31,682.32 10286.31,802.68 10242.93,846.07 10242.93,2709.93 10290,2757 10290,4607 10242.93,4654.07 v3(10242.93,4751.06)
RST: J5.81 J23.14 J24.14 J25.14 | length 8739.2
  Top Layer w10: J5.81@8043.82,7366.21 8043.82,7394.57 8055.5,7406.25 8253.2,7406.25 8267.52,7420.58 8685.53,7420.58 8860.88,7245.23 9163.46,7245.23 9224.57,7184.13 9224.93,7184.13 9605.79,6803.27 9605.79,6319.74 10481.5,5444.03 10481.5,5267.66 10504.87,5244.28 10504.87,5119.7 10435.18,5050 v2(10420,5050)
  Top Layer w20: J23.14@10342.93,574.56 v3(10342.93,638.93) ; J24.14@10342.93,2630.62 v3(10342.93,2694.99) ; J25.14@10342.93,4686.69 v3(10342.93,4751.06)
  Pwr Layer w10: v3(10342.93,638.93) 10386.31,682.32 10386.31,842.68 10342.93,886.07 v3(10342.93,2694.99) 10392,2744.06 10392,4617 10342.93,4666.07 v3(10342.93,4751.06) 10391,4799.13 10391,4964 10420,4993 v2(10420,5050)
RY_A: J5.86 R197.1 | length 11854.7
  Top Layer w10: R197.1@825.5,3502 v1(825.5,3549.5) ; J5.86@8106.81,7452.19 J5.86@8106.81,7500.07
  Bottom Layer w10: v1(825.5,3549.5) 825.5,3588.77 1030,3793.28 1030,5201.85 969.25,5262.6 969.25,5462 1005.76,5498.51 1005.76,5806.1 1070.01,5870.35 1070.01,7601.46 1213.92,7745.38 5315.74,7745.38 5679.62,7381.5 6097.94,7381.5 6495.32,7778.87 7656.4,7778.87 7943.15,7492.13 8078.36,7492.13 8111,7459.49 v2(8111,7452)
RY_B: J5.88 R198.1 | length 9995.2
  Top Layer w10: R198.1@825.5,5444 829.5,5440 v1(920,5440) ; J5.88@8138.3,7500.07 8138.3,7460.7 J5.88@8146,7453
  Bottom Layer w10: v1(920,5440) 987.88,5507.88 987.88,5813.5 1049.66,5875.29 1049.66,7606.4 1206.52,7763.25 5323.15,7763.25 5687.03,7399.37 6090.54,7399.37 6487.92,7796.75 7663.81,7796.75 7950.56,7510 8093,7510 v2(8154,7449)
RY_C: J5.90 R199.1 | length 7902.4
  Top Layer w10: R199.1@825.5,7659 v1(879,7659) ; J5.90@8169.8,7500.07 v2(8169.8,7605.8)
  Bottom Layer w10: v1(879,7659) 1001.13,7781.13 5330.55,7781.13 5694.43,7417.24 6082.52,7417.24 6479.9,7814.62 7671.21,7814.62 7880.03,7605.8 v2(8169.8,7605.8)
RY_N: J5.92 R200.1 | length 14465
  Top Layer w10: R200.1@980.5,1644 v1(980.5,1693.5) ; J5.92@8201.3,7500.07 8201.29,7595.3 8239,7633 v2(8263,7633)
  Bottom Layer w10: v1(980.5,1693.5) 1040,1753.01 1040,2463.74 796.62,2707.12 796.62,3584.72 807.62,3595.72 807.62,3596.18 1012,3800.56 1012,5183.79 890,5305.79 890,5480 969.25,5559.25 969.25,5820.15 1031.79,5882.69 1031.79,7402 854.34,7579.45 850.13,7579.45 850.13,7670.96 978.17,7799 5337.95,7799 5701.84,7435.12 6075.12,7435.12 6472.5,7832.5 7679.81,7832.5 7879.3,7633 v2(8263,7633)
SD_CLKI: R34.1 R36.1 R163.1 R164.1 R165.1 U1.7 U5.7 U8.7 | length 18801.8
  Top Layer w10: v2(1180,5370) 1890.46,5370 v2(1891.7,5371.24) ; v2(2059.45,404.55) U1.7@2059.45,465.43 ; v2(2059.45,2954.55) U5.7@2059.45,3015.43 ; v2(2059.45,5454.55) U8.7@2059.45,5515.43 ; R34.1@7702,7134.54 v2(7753.53,7134.54) ; v2(7897.16,7134.54) 7945.54,7134.54 R36.1@7948.53,7137.53 ; v2(8281.63,7134.54) R163.1@8330,7134.54 ; R163.1@8331,7135.54 R165.1@8516,7135.54
  Bottom Layer w10: v2@1177.51,5371.51 1166,5360 1166,3728 970,3532 970,3162.37 1186,2946.37 1186,2493 1199,2480 ; v2(1180,5370) 1204.47,5394.47 1204.47,5774.34 1225.13,5794.99 1225.13,6708.11 ; 1226.5,6709.49 1225.13,6708.11 ; v2(1891.7,5371.24) 1976.14,5371.24 v2(2059.45,5454.55) ; v2(2059.45,404.55) 1914.9,260 1279.26,260 1186,353.26 1186,2480 1199,2480 ; v2(2059.45,2954.55) 2047.87,2942.98 2047.87,2733.04 1794.83,2480 1199,2480 ; v2(8281.63,7134.54) v2(7897.16,7134.54) v2(7753.53,7134.54) 7569.46,7134.54 7420,7284 7420,7645.51 7358.13,7707.38 6524.93,7707.38 6127.56,7310 5650.01,7310 5286.13,7673.88 1467.88,7673.88 1225.13,7431.13 1225.13,6708.11
SD_DATA_IG_A: J5.99 R146.2 | length 16488.3
  Top Layer w10: v2(1848.04,190) 1848.04,244.04 1892.5,288.5 R146.2@1955,288.5 ; v2(8263,7169) 8263,7212 8327.28,7276.28 J5.99@8327.28,7366.21
  Bottom Layer w10: v2(1848.04,190) 1230.34,190 1119,301.34 1119,2940.19 915,3144.19 915,3565 1115.13,3765.13 1115.13,5750.22 1179.38,5814.47 1179.38,7494.38 1376.76,7691.76 5293.53,7691.76 5657.41,7327.87 6120.15,7327.87 6517.53,7725.25 7365.53,7725.25 7437.87,7652.91 7437.87,7291.4 7560.28,7169 v2(8263,7169)
SD_DATA_IG_B: J5.103 R149.2 | length 14096.9
  Top Layer w10: v2(1810.56,2838.5) R149.2@1955,2838.5 ; v2(8380,7255) 8390.27,7265.27 J5.103@8390.27,7366.21
  Pwr Layer w10: v2(1040,2881.99) 1767.07,2881.99 v2(1810.56,2838.5)
  Bottom Layer w10: v2(1040,2881.99) 1040,2952.65 860,3132.65 860,3598 1050,3788 1050,5207.13 987.13,5270 987.13,5454.6 1023.63,5491.1 1023.63,5798.7 1087.88,5862.95 1087.88,7594.06 1221.33,7727.5 5308.34,7727.5 5672.22,7363.62 6105.35,7363.62 6502.72,7761 7380.34,7761 7473.62,7667.72 7473.62,7306.38 7562.87,7217.13 8342.13,7217.13 v2(8380,7255)
SD_DATA_IG_C: J5.107 R152.2 | length 11445.3
  Top Layer w10: v2(1045,5342) 1951.5,5342 R152.2@1955,5338.5 ; J5.107@8453.26,7366.21 8453.26,7265.27 v2(8461.4,7257.14)
  Bottom Layer w10: v2(1045,5342) 1069.38,5366.38 1069.38,5779.75 1133.63,5844 1133.63,7553.63 1289.63,7709.63 5300.94,7709.63 5664.82,7345.75 6112.75,7345.75 6510.13,7743.13 7372.94,7743.13 7455.75,7660.31 7455.75,7298.81 7560.55,7194 8398.26,7194 v2(8461.4,7257.14)
TEMP_A: C39.2 J5.12 R52.2 R58.2 | length 10776.2
  Top Layer w10: J5.12@6815.47,7500.07 v2(6815.47,7615.54) ; R58.2@9901.5,1113.75 R52.2@9901.5,1049.2 9966.79,1049.2 C39.2@9967,1049 9973,1055 9968,1060 v2(9968,1128)
  Pwr Layer w10: v2(6825,2002) 6863,2002 7129,2268 9912,2268 10004,2176 10004,1164 v2(9968,1128)
  Bottom Layer w10: v2(6815.47,7615.54) 6815.47,7462.71 6480,7127.24 6480,7123.46 6470.67,7114.13 6470.67,6288.77 6654.01,6105.44 6654.01,4503.77 6797,4360.78 6797,3941 6850,3888 6850,3466.03 6664.5,3280.53 6664.5,2534.38 6824,2374.89 6824,2003 v2(6825,2002)
TEMP_AMB: C52.2 J5.20 R93.2 | length 1627
  Top Layer w10: R93.2@6359,6943.5 6296.55,6943.5 C52.2@6296,6944.05 6269,6971.05 6269,7582 6397,7710 6906,7710 6941.45,7674.55 J5.20@6941.45,7500.07
TEMP_B: C42.2 J5.14 R62.2 R65.2 | length 10228
  Top Layer w10: J5.14@6846,7501.04 v2(6846,7646) ; v2(9640,2530) 9640,2600 9670,2630 9670,2864.14 9728.86,2923 9865.61,2923 9970,3027.39 C42.2@9970,3106.39 9968.87,3105.27 R62.2@9901.5,3105.27 R65.2@9901.5,3166.27 ; R65.2@9910,3166.27 R65.2@9910,3169.81
  Top Layer w12: J5.14@6846,7501.04 J5.14@6846.96,7500.07
  Pwr Layer w10: v2(6857,2040) 7107.39,2290.39 9585.92,2290.39 9640,2344.47 v2(9640,2530)
  Bottom Layer w10: v2(6846,7646) 6846,7467.97 6500,7121.97 6500,7118.18 6488.54,7106.73 6488.54,6296.18 6671.88,6112.84 6671.88,4511.17 6814.87,4368.18 6814.87,3948.4 6867.87,3895.4 6867.87,3458.62 6682.38,3273.13 6682.38,2541.79 6857,2367.17 v2(6857,2040)
TEMP_C: C50.2 J5.18 R77.2 R92.2 | length 7493.6
  Top Layer w10: v2(6908.99,7646) 6908.99,7501.04 J5.18@6909.96,7500.07 ; v2(9604.82,4600.35) 9665.21,4660.74 9665.21,4918.21 9727,4980 9810.28,4980 9972,5141.72 C50.2@9972,5162 9971.33,5161.33 R77.2@9901.5,5161.33 R92.2@9901.5,5225.87
  Pwr Layer w10: v1(6710,5120) 6690,5100 6690,4520 6830,4380 9384.47,4380 v2(9604.82,4600.35)
  Bottom Layer w10: v1(6710,5120) 6689.76,5140.24 6689.76,6120.24 6506.42,6303.58 6506.42,7099.32 6908.99,7501.9 v2(6908.99,7646)
V1.65: C118.1 R178.2 R179.2 TP1.1 U24.1 | length 5642.2
  Top Layer w10: v1(8304.48,6191.88) v1@8304.48,6195.89
  Top Layer w20: R179.2@6628.5,6330 6628.5,6233.38 6678.38,6183.5 7389.5,6183.5 v1(7445.39,6239.39) ; U24.1@10865.74,6389.64 10928.51,6389.64 C118.1@10930.61,6387.54 11076.54,6387.54 TP1.1@11077,6388
  Top Layer w30: v1@8304.48,6195.89 R178.2@8304.48,6248.38 R178.2@8305.09,6249
  Pwr Layer w20: v1(8304.48,6191.88) 8456.36,6040 9922.41,6040 10632.41,6750 10984.46,6750 11077,6657.46 TP1.1@11077,6388
  Bottom Layer w20: v1(7445.39,6239.39) 7445.39,6290.39 7478,6323 7857,6323 7988.12,6191.88 v1(8304.48,6191.88)
VA_N: C84.2 R94.2 R98.2 U19.2 | length 10778.1
  Top Layer w10: R98.2@1795,2520 1877,2520 1923.05,2566.05 v1(2092.72,2566.05) ; v2(8182,6257) 8182,6318 8196.75,6332.75 C84.2@8196.75,6408 8196.83,6408.08 U19.2@8196.83,6497.89
  Pwr Layer w10: v1(2092.72,2566.05) 2094.28,2564.49 2117.86,2564.49 2139.21,2585.84 4800.39,2585.84 5063.62,2849.07 5063.62,6519.9 5234.6,6690.87 6342.9,6690.87 6832.39,6201.38 8164.56,6201.38 8199.06,6235.88 8199.06,6244.16 8193.21,6250.02 8192.77,6250.02 8185.79,6257 v2(8182,6257)
VA_P: R103.2 R104.2 U19.3 | length 10607.7
  Top Layer w10: R103.2@2025,2520 v1(2120,2520) ; v2@8234.33,6257 8234.33,6355.63 R104.2@8279.7,6401 8246.83,6433.87 U19.3@8246.83,6497.89
  Pwr Layer w10: v1(2120,2520) 2121.25,2521.25 2121.25,2542.59 2146.61,2567.96 4807.8,2567.96 5081.5,2841.66 5081.5,6512.5 5242,6673 6335.49,6673 6824.99,6183.5 8171.97,6183.5 8216.94,6228.48 8216.94,6244.16 8222.8,6250.02 8223.23,6250.02 8230.21,6257 v2(8234,6257)
VB_N: C86.2 R105.2 R109.2 U19.6 | length 8767.1
  Top Layer w10: U19.6@8396.83,6497.89 8396.83,6465.67 C86.2@8454.5,6408 8454.5,6331.5 8468,6318 v2(8468,6257)
  Top Layer w15: R109.2@1746.45,5019 v1(1809.9,5019)
  Pwr Layer w10: v1(1809.9,5019) 1925.9,5019 1963.27,5056.38 4786.93,5056.38 4992.13,5261.57 4992.13,6549.51 5204.98,6762.37 6372.51,6762.37 6580.39,6554.49 6823.27,6554.49 7140.63,6237.13 7375.02,6237.13 7471.64,6333.75 8402.71,6333.75 8450.94,6285.52 8450.94,6269.84 8456.8,6263.98 8457.23,6263.98 8464.21,6257 v2(8468,6257)
VB_P: R115.2 R116.2 U19.5 | length 8480.7
  Top Layer w10: U19.5@8346.83,6497.89 8346.83,6423.87 8416,6354.7 v2(8416,6257)
  Top Layer w15: R115.2@1997,5019 v1(2060.45,5019)
  Pwr Layer w10: v1(2060.45,5019) 2060.45,5022.45 2076.51,5038.5 4794.34,5038.5 5010,5254.17 5010,6542.11 5212.39,6744.5 6365.11,6744.5 6572.99,6536.61 6815.86,6536.61 7133.22,6219.25 7382.42,6219.25 7479.04,6315.87 8395.31,6315.87 8433.06,6278.12 8433.06,6269.84 8427.21,6263.98 8426.77,6263.98 8419.79,6257 v2(8416,6257)
VC_N: C88.2 R117.2 R121.2 U19.9 | length 7670.9
  Top Layer w10: R121.2@1791.06,7383 1881.54,7383 1907.4,7408.86 1907.4,7601.18 1990.47,7684.25 5211.03,7684.25 5527.87,7367.4 5527.87,7103.4 5636.34,6994.94 6048.94,6994.94 v2(6062,7008) ; U19.9@8396.83,6712.46 8396.83,6797.33 C88.2@8408.5,6809 8408.5,6885.5 8425,6902 v2(8425,6963)
  Pwr Layer w10: v2(6062,7008) 6074,6996 6645.72,6996 6710.72,7061 8359.78,7061 8409.5,7011.28 8409.5,6978.5 v2(8425,6963)
VC_P: R126.2 R127.2 U19.10 | length 7631.3
  Top Layer w10: R126.2@2041.61,7383 1951.13,7383 1925.28,7408.86 1925.28,7593.78 1997.88,7666.38 5203.62,7666.38 5510,7360 5510,7096 5628.94,6977.06 6048.94,6977.06 v2(6062,6964) ; U19.10@8346.83,6712.46 8346.83,6796.17 R127.2@8327,6816 8339,6816 8374.13,6851.13 8374.13,6962.87 v2(8374,6963)
  Pwr Layer w10: v2(6062,6964) 6074,6976 6654,6976 6719,7041 8351.5,7041 8389.5,7003 8389.5,6978.5 v2(8374,6963)
VDC_SEN: J5.42 J38.2 | length 5496
  Top Layer w10: J5.42@7287.91,7500.07 7287.91,7660.91 7348,7721 v2(7623,7721) ; v1(9370,7099) 9370,7064.33 9623.66,6810.67 9623.66,6328.42 9762.08,6190 11452.17,6190 J38.2@11600,6042.18
  Bottom Layer w10: v2(7623,7721) 7689,7721 8060,7350 8572.4,7350 8823.4,7099 v1(9370,7099)
VG_SEN_A: C51.2 J5.15 R46.2 | length 1166.9
  Top Layer w10: R46.2@6860.11,6397.5 C51.2@6796.11,6397.5 6796.11,6453.56 6675.35,6574.33 6675.35,6995.35 6878.46,7198.46 J5.15@6878.46,7366.21
VG_SEN_B: C54.2 J5.31 R71.2 | length 1318.3
  Top Layer w10: J5.31@7130.43,7366.21 7130.43,7201.57 7297.87,7034.13 7384.6,7034.13 7567,6851.72 7567,6435 7529.5,6397.5 R71.2@7427.11,6397.5
VG_SEN_C: C55.2 J5.28 R84.2 | length 1191.9
  Top Layer w10: v2(7067,7640) 7067.44,7639.56 J5.28@7067.44,7500.07 ; v2@7074,7098 7176.87,6995.13 7338.87,6995.13 7383,6951 R84.2@7383,6874.5 C55.2@7448,6874.5
  Bottom Layer w10: v2(7067,7640) 7067,7101 v2@7068,7100
  other v2: 7069,7099
Vinv_A: C28.2 C65.1 C93.2 C94.2 C97.1 C99.2 C101.1 C103.2 C105.1 D13.3 D26.1 D28.2 K1.1 R5.2 R147.1 RF1.2 T1.5 U1.4 U10.1 | length 1714.2
  Top Layer w10: R5.2@1871.06,1350 1997,1350 2021.95,1325.05 2021.95,1174 R147.1@1999.45,1151.5
  Top Layer w20: D13.3@1820.76,1052 v1(1820.76,1095.76) ; v2(1909,895) 1909.43,894.57 U1.4@1959.45,894.57 ; v1(2385,564) D26.1@2385,613.86 ; v1(2482,626) 2482,672.53 D28.2@2485,675.53 ; v1(2494,536) 2495,535 C105.1@2552.91,535 2552.91,511.09 2610,454 2610,368 2625.4,352.6 2715.9,352.6 C99.2@2740,328.5 v1(2740,237) ; v1(2538.5,655) C101.1@2585,655 ; v1(2547,735) C103.2@2593.5,735
  Top Layer w30: v1(1871.06,1156.86) R5.2@1871.06,1350 ; v1(2209.45,769.55) 2209.45,826.54 v1(2266.43,826.54)
  Pwr Layer w50: v1(3103.59,243) 3103.59,141.69 C65.1@3115.28,130
  Bottom Layer w20: v1(2622,293) 2622.09,292.91 2732.09,292.91 2740,285 v1(2740,237)
  other v1: 3025,353 3025,419 3025,485 1782.9,1270 1782.9,1332 1782.9,1392 1782.9,1452
Vinv_B: C35.2 C67.1 C95.2 C96.2 C98.1 C100.2 C102.1 C104.2 C106.1 D15.3 D27.1 D29.2 K2.1 R41.2 R150.1 RF2.2 T2.5 U5.4 U21.1 | length 1712
  Top Layer w10: R41.2@1871.06,3900 1997,3900 2021.95,3875.05 2021.95,3724 R150.1@1999.45,3701.5
  Top Layer w20: D15.3@1820.76,3602 v1(1820.76,3645.76) ; v2(1909,3445) 1909.43,3444.57 U5.4@1959.45,3444.57 ; v1(2385,3114) D27.1@2385,3163.86 ; v1(2482,3176) 2482,3222.53 D29.2@2485,3225.53 ; v1(2494,3086) 2495,3085 C106.1@2552.91,3085 2552.91,3061.09 2610,3004 2610,2918 2625.4,2902.6 2715.9,2902.6 C100.2@2740,2878.5 v1(2740,2787) ; v1(2538.5,3205) C102.1@2585,3205 ; v1(2547,3285) C104.2@2593.5,3285
  Top Layer w30: v1(1871.06,3706.86) R41.2@1871.06,3900 ; v1(2209.45,3319.55) C35.2@2209.45,3376.54 v1(2266.43,3376.54)
  Pwr Layer w50: v1(3100,2784.89) 3100,2702.06 C67.1@3123.15,2678.91
  Bottom Layer w20: v1(2622,2843) 2622.09,2842.91 2732.09,2842.91 2740,2835 v1(2740,2787)
  other v1: 3025,2903 3025,2969 3025,3035 1782.9,3835 1782.9,3893 1782.9,3953 1782.9,4013
Vinv_C: C18.2 C68.1 C110.2 C111.2 C112.1 C113.2 C114.1 C115.2 C116.1 D17.3 D32.1 D33.2 K3.1 R47.2 R153.1 RF3.2 T3.5 U8.4 U23.1 | length 1708.5
  Top Layer w10: R47.2@1871.06,6400 1997,6400 2021.95,6375.05 2021.95,6224 R153.1@1999.45,6201.5
  Top Layer w20: D17.3@1820.76,6102 v1(1820.76,6145.76) ; v2(1909,5945) 1909.43,5944.57 U8.4@1959.45,5944.57 ; v1(2385,5614) D32.1@2385,5663.86 ; v1(2482,5676) 2482,5722.53 D33.2@2485,5725.53 ; v1(2494,5586) 2495,5585 C116.1@2552.91,5585 2552.91,5561.09 2610,5504 2610,5418 2625.4,5402.6 2715.9,5402.6 C113.2@2740,5378.5 v1(2740,5287) ; v1(2538.5,5705) C114.1@2585,5705 ; v1(2547,5785) C115.2@2593.5,5785
  Top Layer w30: v1(1871.06,6206.86) R47.2@1871.06,6400 ; v1(2209.45,5819.55) C18.2@2209.45,5876.54 v1(2266.43,5876.54)
  Pwr Layer w50: v1(3106.9,5287) 3106.9,5192.25 C68.1@3119.15,5180
  Bottom Layer w20: v1(2622,5343) 2622.09,5342.91 2732.09,5342.91 2740,5335 v1(2740,5287)
  other v1: 3025,5403 3025,5469 3025,5535 1782.9,6322 1782.9,6377 1782.9,6437 1782.9,6495.5
VINV_SEN_A: C59.2 J5.21 R99.2 | length 1853.7
  Top Layer w10: J5.21@6972.95,7366.21 6972.95,7242.05 7202,7013 7380.44,7013 7548,6845.44 7548,6457 v2(7530,6439) ; v2@7976.7,6438.7 7982.9,6432.5 8038.3,6432.5 8038.7,6432.1 R99.2@8038.7,6367.5
  Bottom Layer w10: v2(7530,6439) v2(7977,6439)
